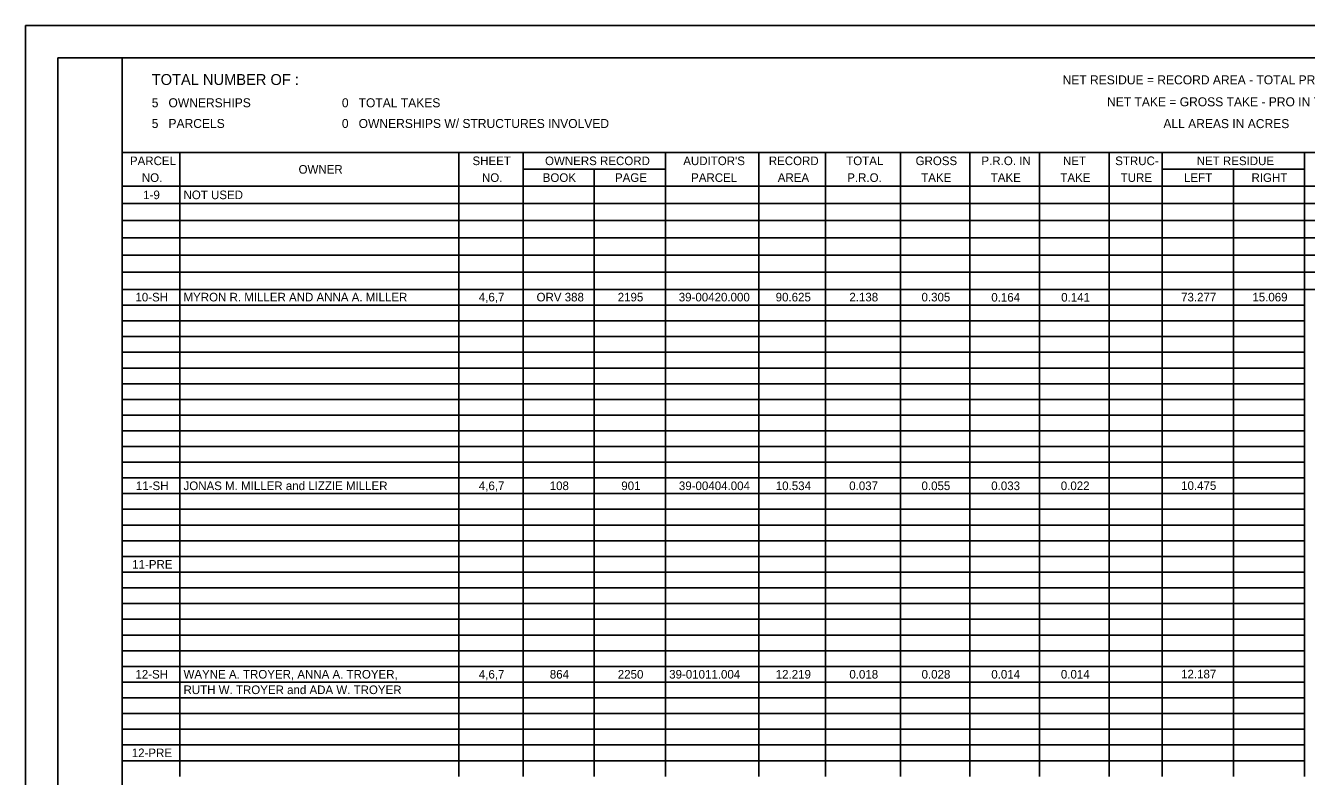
# Model space of a CAD drawing. Extents: x 0 to 34, y 0 to 22.
# Drawn here: x 0 to 19.9, y 10.33 to 22 of the extents above; entities that cross this region are included whole.
import ezdxf

# ---------------------------------------------------------------- set-up
doc = ezdxf.new("R2010")
doc.units = 0
for name, color, linetype in [('SH_Border', 7, 'Continuous'), ('SH_Cut_Line', 7, 'Continuous'), ('SH_Text', 7, 'Continuous')]:
    doc.layers.add(name, color=color, linetype=linetype)

msp = doc.modelspace()

# ---------------------------------------------------------------- linework, layer by layer
at = {"layer": 'SH_Border'}
for points in [[(0.5, 21.5), (1.5, 21.5), (1.5, 0.5), (0.5, 0.5)], [(1.5, 21.5), (33.5, 21.5), (33.5, 0.5), (1.5, 0.5)]]:
    msp.add_lwpolyline(points, close=True, dxfattribs=at)
at = {"layer": 'SH_Cut_Line'}
msp.add_lwpolyline([(0, 0), (34, 0), (34, 22), (0, 22)], close=True, dxfattribs=at)
at = {"layer": 'SH_Text'}
for p, q in [((1.5, 20.027), (7.73, 20.027)), ((1.5, 20.027), (1.5, 18.702)), ((2.395, 20.027), (2.395, 18.434)), ((6.731, 20.027), (6.731, 18.434)), ((7.73, 20.027), (14.669, 20.027)), ((7.73, 20.027), (7.73, 18.434)), ((9.939, 20.027), (9.939, 18.434)), ((11.392, 20.027), (11.392, 18.434)), ((12.426, 20.027), (12.426, 18.434)), ((13.588, 20.027), (13.588, 18.434)), ((14.669, 20.027), (32, 20.027)), ((14.669, 20.027), (14.669, 18.434)), ((15.75, 20.027), (15.75, 18.434)), ((16.831, 20.027), (16.831, 18.434)), ((17.657, 20.027), (17.657, 18.434)), ((19.865, 20.027), (19.865, 18.434)), ((7.73, 19.771), (9.939, 19.771)), ((8.834, 19.771), (8.834, 18.434)), ((17.657, 19.771), (19.865, 19.771)), ((18.761, 19.771), (18.761, 18.434)), ((1.5, 19.504), (7.73, 19.504)), ((7.73, 19.504), (14.669, 19.504)), ((14.669, 19.504), (32, 19.504)), ((1.5, 19.237), (7.73, 19.237)), ((7.73, 19.237), (14.669, 19.237)), ((14.669, 19.237), (32, 19.237)), ((1.5, 18.969), (7.73, 18.969)), ((7.73, 18.969), (14.669, 18.969)), ((14.669, 18.969), (32, 18.969)), ((1.5, 18.702), (7.73, 18.702)), ((7.73, 18.702), (14.669, 18.702)), ((14.669, 18.702), (32, 18.702)), ((1.5, 18.434), (7.73, 18.434)), ((2.395, 18.434), (2.395, 18.167)), ((6.731, 18.434), (6.731, 18.167)), ((7.73, 18.434), (14.669, 18.434)), ((7.73, 18.434), (7.73, 18.167)), ((8.834, 18.434), (8.834, 18.167)), ((9.939, 18.434), (9.939, 18.167)), ((11.392, 18.434), (11.392, 18.167)), ((12.426, 18.434), (12.426, 18.167)), ((13.588, 18.434), (13.588, 18.167)), ((14.669, 18.434), (32, 18.434)), ((14.669, 18.434), (14.669, 18.167)), ((15.75, 18.434), (15.75, 18.167)), ((16.831, 18.434), (16.831, 18.167)), ((17.657, 18.434), (17.657, 18.167)), ((18.761, 18.434), (18.761, 18.167)), ((19.865, 18.434), (19.865, 18.167)), ((1.5, 18.167), (7.73, 18.167)), ((2.395, 18.167), (2.395, 17.9)), ((6.731, 18.167), (6.731, 17.9)), ((7.73, 18.167), (14.669, 18.167)), ((7.73, 18.167), (7.73, 17.9)), ((8.834, 18.167), (8.834, 17.9)), ((9.939, 18.167), (9.939, 17.9)), ((11.392, 18.167), (11.392, 17.9)), ((12.426, 18.167), (12.426, 17.9)), ((13.588, 18.167), (13.588, 17.9)), ((14.669, 18.167), (32, 18.167)), ((14.669, 18.167), (14.669, 17.9)), ((15.75, 18.167), (15.75, 17.9)), ((16.831, 18.167), (16.831, 17.9)), ((17.657, 18.167), (17.657, 17.9)), ((18.761, 18.167), (18.761, 17.9)), ((19.865, 18.167), (19.865, 17.9)), ((1.5, 17.9), (7.73, 17.9)), ((2.395, 17.9), (2.395, 15.947)), ((6.731, 17.9), (6.731, 15.947)), ((7.73, 17.9), (14.669, 17.9)), ((7.73, 17.9), (7.73, 15.947)), ((8.834, 17.9), (8.834, 15.947)), ((9.939, 17.9), (9.939, 15.947)), ((11.392, 17.9), (11.392, 15.947)), ((12.426, 17.9), (12.426, 15.947)), ((13.588, 17.9), (13.588, 15.947)), ((14.669, 17.9), (32, 17.9)), ((14.669, 17.9), (14.669, 15.947)), ((15.75, 17.9), (15.75, 15.947)), ((16.831, 17.9), (16.831, 15.947)), ((17.657, 17.9), (17.657, 15.947)), ((18.761, 17.9), (18.761, 15.947)), ((19.865, 17.9), (19.865, 15.947)), ((1.5, 17.656), (7.73, 17.656)), ((7.73, 17.656), (14.669, 17.656)), ((14.669, 17.656), (19.865, 17.656)), ((1.5, 17.412), (7.73, 17.412)), ((7.73, 17.412), (14.669, 17.412)), ((14.669, 17.412), (19.865, 17.412)), ((1.5, 17.168), (7.73, 17.168)), ((7.73, 17.168), (14.669, 17.168)), ((14.669, 17.168), (19.865, 17.168)), ((1.5, 16.923), (7.73, 16.923)), ((7.73, 16.923), (14.669, 16.923)), ((14.669, 16.923), (19.865, 16.923)), ((1.5, 16.679), (7.73, 16.679)), ((7.73, 16.679), (14.669, 16.679)), ((14.669, 16.679), (19.865, 16.679)), ((1.5, 16.435), (7.73, 16.435)), ((7.73, 16.435), (14.669, 16.435)), ((14.669, 16.435), (19.865, 16.435)), ((1.5, 16.191), (7.73, 16.191)), ((7.73, 16.191), (14.669, 16.191)), ((14.669, 16.191), (19.865, 16.191)), ((1.5, 15.947), (7.73, 15.947)), ((2.395, 15.947), (2.395, 15.703)), ((6.731, 15.947), (6.731, 15.703)), ((7.73, 15.947), (14.669, 15.947)), ((7.73, 15.947), (7.73, 15.703)), ((8.834, 15.947), (8.834, 15.703)), ((9.939, 15.947), (9.939, 15.703)), ((11.392, 15.947), (11.392, 15.703)), ((12.426, 15.947), (12.426, 15.703)), ((13.588, 15.947), (13.588, 15.703)), ((14.669, 15.947), (19.865, 15.947)), ((14.669, 15.947), (14.669, 15.703)), ((15.75, 15.947), (15.75, 15.703)), ((16.831, 15.947), (16.831, 15.703)), ((17.657, 15.947), (17.657, 15.703)), ((18.761, 15.947), (18.761, 15.703)), ((19.865, 15.947), (19.865, 15.703)), ((1.5, 15.703), (7.73, 15.703)), ((2.395, 15.703), (2.395, 15.215)), ((6.731, 15.703), (6.731, 15.215)), ((7.73, 15.703), (14.669, 15.703)), ((7.73, 15.703), (7.73, 15.215)), ((8.834, 15.703), (8.834, 15.215)), ((9.939, 15.703), (9.939, 15.215)), ((11.392, 15.703), (11.392, 15.215)), ((12.426, 15.703), (12.426, 15.215)), ((13.588, 15.703), (13.588, 15.215)), ((14.669, 15.703), (19.865, 15.703)), ((14.669, 15.703), (14.669, 15.215)), ((15.75, 15.703), (15.75, 15.215)), ((16.831, 15.703), (16.831, 15.215)), ((17.657, 15.703), (17.657, 15.215)), ((18.761, 15.703), (18.761, 15.215)), ((19.865, 15.703), (19.865, 15.215)), ((1.5, 15.459), (7.73, 15.459)), ((7.73, 15.459), (14.669, 15.459)), ((14.669, 15.459), (19.865, 15.459)), ((1.5, 15.215), (7.73, 15.215)), ((2.395, 15.215), (2.395, 14.971)), ((6.731, 15.215), (6.731, 14.971)), ((7.73, 15.215), (14.669, 15.215)), ((7.73, 15.215), (7.73, 14.971)), ((8.834, 15.215), (8.834, 14.971)), ((9.939, 15.215), (9.939, 14.971)), ((11.392, 15.215), (11.392, 14.971)), ((12.426, 15.215), (12.426, 14.971)), ((13.588, 15.215), (13.588, 14.971)), ((14.669, 15.215), (19.865, 15.215)), ((14.669, 15.215), (14.669, 14.971)), ((15.75, 15.215), (15.75, 14.971)), ((16.831, 15.215), (16.831, 14.971)), ((17.657, 15.215), (17.657, 14.971)), ((18.761, 15.215), (18.761, 14.971)), ((19.865, 15.215), (19.865, 14.971)), ((1.5, 14.971), (7.73, 14.971)), ((1.5, 14.971), (1.5, 14.727)), ((2.395, 14.971), (2.395, 14.727)), ((6.731, 14.971), (6.731, 14.727)), ((7.73, 14.971), (14.669, 14.971)), ((7.73, 14.971), (7.73, 14.727)), ((8.834, 14.971), (8.834, 14.727)), ((9.939, 14.971), (9.939, 14.727)), ((11.392, 14.971), (11.392, 14.727)), ((12.426, 14.971), (12.426, 14.727)), ((13.588, 14.971), (13.588, 14.727)), ((14.669, 14.971), (19.865, 14.971)), ((14.669, 14.971), (14.669, 14.727)), ((15.75, 14.971), (15.75, 14.727)), ((16.831, 14.971), (16.831, 14.727)), ((17.657, 14.971), (17.657, 14.727)), ((18.761, 14.971), (18.761, 14.727)), ((19.865, 14.971), (19.865, 14.727)), ((1.5, 14.727), (7.73, 14.727)), ((1.5, 14.727), (1.5, 14.483)), ((2.395, 14.727), (2.395, 14.483)), ((6.731, 14.727), (6.731, 14.483)), ((7.73, 14.727), (14.669, 14.727)), ((7.73, 14.727), (7.73, 14.483)), ((8.834, 14.727), (8.834, 14.483)), ((9.939, 14.727), (9.939, 14.483)), ((11.392, 14.727), (11.392, 14.483)), ((12.426, 14.727), (12.426, 14.483)), ((13.588, 14.727), (13.588, 14.483)), ((14.669, 14.727), (19.865, 14.727)), ((14.669, 14.727), (14.669, 14.483)), ((15.75, 14.727), (15.75, 14.483)), ((16.831, 14.727), (16.831, 14.483)), ((17.657, 14.727), (17.657, 14.483)), ((18.761, 14.727), (18.761, 14.483)), ((19.865, 14.727), (19.865, 14.483)), ((1.5, 14.483), (7.73, 14.483)), ((1.5, 14.483), (1.5, 10.821)), ((2.395, 14.483), (2.395, 10.821)), ((6.731, 14.483), (6.731, 10.821)), ((7.73, 14.483), (14.669, 14.483)), ((7.73, 14.483), (7.73, 10.821)), ((8.834, 14.483), (8.834, 10.821)), ((9.939, 14.483), (9.939, 10.821)), ((11.392, 14.483), (11.392, 10.821)), ((12.426, 14.483), (12.426, 10.821)), ((13.588, 14.483), (13.588, 10.821)), ((14.669, 14.483), (19.865, 14.483)), ((14.669, 14.483), (14.669, 10.821)), ((15.75, 14.483), (15.75, 10.821)), ((16.831, 14.483), (16.831, 10.821)), ((17.657, 14.483), (17.657, 10.821)), ((18.761, 14.483), (18.761, 10.821)), ((19.865, 14.483), (19.865, 10.821)), ((1.5, 14.238), (7.73, 14.238)), ((7.73, 14.238), (14.669, 14.238)), ((14.669, 14.238), (19.865, 14.238)), ((1.5, 13.994), (7.73, 13.994)), ((7.73, 13.994), (14.669, 13.994)), ((14.669, 13.994), (19.865, 13.994)), ((1.5, 13.75), (7.73, 13.75)), ((7.73, 13.75), (14.669, 13.75)), ((14.669, 13.75), (19.865, 13.75)), ((1.5, 13.506), (7.73, 13.506)), ((7.73, 13.506), (14.669, 13.506)), ((14.669, 13.506), (19.865, 13.506)), ((1.5, 13.262), (7.73, 13.262)), ((7.73, 13.262), (14.669, 13.262)), ((14.669, 13.262), (19.865, 13.262)), ((1.5, 13.018), (7.73, 13.018)), ((7.73, 13.018), (14.669, 13.018)), ((14.669, 13.018), (19.865, 13.018)), ((1.5, 12.774), (7.73, 12.774)), ((7.73, 12.774), (14.669, 12.774)), ((14.669, 12.774), (19.865, 12.774)), ((1.5, 12.53), (7.73, 12.53)), ((7.73, 12.53), (14.669, 12.53)), ((14.669, 12.53), (19.865, 12.53)), ((1.5, 12.286), (7.73, 12.286)), ((7.73, 12.286), (14.669, 12.286)), ((14.669, 12.286), (19.865, 12.286)), ((1.5, 12.042), (7.73, 12.042)), ((7.73, 12.042), (14.669, 12.042)), ((14.669, 12.042), (19.865, 12.042)), ((1.5, 11.797), (7.73, 11.797)), ((7.73, 11.797), (14.669, 11.797)), ((14.669, 11.797), (19.865, 11.797)), ((1.5, 11.553), (7.73, 11.553)), ((7.73, 11.553), (14.669, 11.553)), ((14.669, 11.553), (19.865, 11.553)), ((1.5, 11.309), (7.73, 11.309)), ((7.73, 11.309), (14.669, 11.309)), ((14.669, 11.309), (19.865, 11.309)), ((1.5, 11.065), (7.73, 11.065)), ((7.73, 11.065), (14.669, 11.065)), ((14.669, 11.065), (19.865, 11.065)), ((1.5, 10.821), (7.73, 10.821)), ((1.5, 10.821), (1.5, 10.577)), ((2.395, 10.821), (2.395, 10.577)), ((6.731, 10.821), (6.731, 10.577)), ((7.73, 10.821), (14.669, 10.821)), ((7.73, 10.821), (7.73, 10.577)), ((8.834, 10.821), (8.834, 10.577)), ((9.939, 10.821), (9.939, 10.577)), ((11.392, 10.821), (11.392, 10.577)), ((12.426, 10.821), (12.426, 10.577)), ((13.588, 10.821), (13.588, 10.577)), ((14.669, 10.821), (19.865, 10.821)), ((14.669, 10.821), (14.669, 10.577)), ((15.75, 10.821), (15.75, 10.577)), ((16.831, 10.821), (16.831, 10.577)), ((17.657, 10.821), (17.657, 10.577)), ((18.761, 10.821), (18.761, 10.577)), ((19.865, 10.821), (19.865, 10.577)), ((1.5, 10.577), (7.73, 10.577)), ((1.5, 10.577), (1.5, 10.333)), ((2.395, 10.577), (2.395, 10.333)), ((6.731, 10.577), (6.731, 10.333)), ((7.73, 10.577), (14.669, 10.577)), ((7.73, 10.577), (7.73, 10.333)), ((8.834, 10.577), (8.834, 10.333)), ((9.939, 10.577), (9.939, 10.333)), ((11.392, 10.577), (11.392, 10.333)), ((12.426, 10.577), (12.426, 10.333)), ((13.588, 10.577), (13.588, 10.333)), ((14.669, 10.577), (19.865, 10.577)), ((14.669, 10.577), (14.669, 10.333)), ((15.75, 10.577), (15.75, 10.333)), ((16.831, 10.577), (16.831, 10.333)), ((17.657, 10.577), (17.657, 10.333)), ((18.761, 10.577), (18.761, 10.333)), ((19.865, 10.577), (19.865, 10.333))]:
    msp.add_line(p, q, dxfattribs=at)

# ---------------------------------------------------------------- texts
for s, height, p in [('TOTAL NUMBER OF :', 0.17, (1.959, 21.077)), ('NET RESIDUE = RECORD AREA - TOTAL PRO - NET TAKE', 0.14, (16.108, 21.087)), ('5   OWNERSHIPS', 0.14, (1.959, 20.731)), ('0   TOTAL TAKES', 0.14, (4.913, 20.731)), ('NET TAKE = GROSS TAKE - PRO IN TAKE', 0.14, (16.799, 20.746)), ('5   PARCELS', 0.14, (1.959, 20.409)), ('0   OWNERSHIPS W/ STRUCTURES INVOLVED', 0.14, (4.913, 20.409)), ('ALL AREAS IN ACRES', 0.14, (17.674, 20.407)), ('PARCEL', 0.1337, (1.62, 19.832)), ('SHEET', 0.1337, (6.942, 19.832)), ('OWNERS RECORD', 0.13367, (8.069, 19.832)), ("AUDITOR'S", 0.1337, (10.216, 19.832)), ('RECORD', 0.1337, (11.545, 19.832)), ('TOTAL', 0.1337, (12.747, 19.832)), ('GROSS', 0.1337, (13.825, 19.832)), ('P.R.O. IN', 0.1337, (14.848, 19.832)), ('NET', 0.1337, (16.114, 19.832)), ('STRUC-', 0.1337, (16.926, 19.832)), ('NET RESIDUE', 0.13367, (18.192, 19.832)), ('NO.', 0.1337, (1.806, 19.571)), ('OWNER', 0.1337, (4.24, 19.699)), ('NO.', 0.1337, (7.089, 19.571)), ('BOOK', 0.1337, (8.033, 19.571)), ('PAGE', 0.1337, (9.155, 19.571)), ('PARCEL', 0.1337, (10.338, 19.571)), ('AREA', 0.1337, (11.684, 19.571)), ('P.R.O.', 0.1337, (12.763, 19.571)), ('TAKE', 0.1337, (13.912, 19.571)), ('TAKE', 0.1337, (14.993, 19.571)), ('TAKE', 0.1337, (16.074, 19.571)), ('TURE', 0.1337, (17.011, 19.571)), ('LEFT', 0.1337, (17.995, 19.571)), ('RIGHT', 0.1337, (19.043, 19.571)), ('1-9', 0.1337, (1.827, 19.303)), ('NOT USED', 0.1337, (2.453, 19.303)), ('10-SH', 0.1337, (1.706, 17.714)), ('MYRON R. MILLER AND ANNA A. MILLER', 0.13367, (2.453, 17.714)), ('4,6,7', 0.1337, (7.04, 17.714)), ('ORV 388', 0.1337, (7.937, 17.714)), ('2195', 0.1337, (9.198, 17.714)), ('39-00420.000', 0.13367, (10.146, 17.714)), ('90.625', 0.1337, (11.651, 17.714)), ('2.138', 0.1337, (12.796, 17.714)), ('0.305', 0.1337, (13.917, 17.714)), ('0.164', 0.1337, (15.001, 17.711)), ('0.141', 0.1337, (16.087, 17.711)), ('73.277', 0.1337, (17.949, 17.714)), ('15.069', 0.1337, (19.056, 17.714)), ('JONAS M. MILLER and LIZZIE MILLER', 0.13367, (2.453, 14.782)), ('11-SH', 0.1337, (1.713, 14.782)), ('4,6,7', 0.1337, (7.04, 14.782)), ('108', 0.1337, (8.141, 14.782)), ('901', 0.1337, (9.253, 14.782)), ('39-00404.004', 0.13367, (10.148, 14.782)), ('10.534', 0.1337, (11.653, 14.782)), ('0.037', 0.1337, (12.794, 14.782)), ('0.055', 0.1337, (13.917, 14.782)), ('0.033', 0.1337, (15, 14.782)), ('0.022', 0.1337, (16.08, 14.782)), ('10.475', 0.1337, (17.95, 14.785)), ('11-PRE', 0.1337, (1.656, 13.561)), ('12-SH', 0.1337, (1.706, 11.853)), ('WAYNE A. TROYER, ANNA A. TROYER,', 0.13367, (2.453, 11.853)), ('4,6,7', 0.1337, (7.04, 11.853)), ('864', 0.1337, (8.143, 11.853)), ('2250', 0.1337, (9.199, 11.853)), ('39-01011.004', 0.13367, (9.997, 11.853)), ('12.219', 0.1337, (11.652, 11.853)), ('0.018', 0.1337, (12.796, 11.853)), ('0.028', 0.1337, (13.918, 11.853)), ('0.014', 0.1337, (15.001, 11.853)), ('0.014', 0.1337, (16.082, 11.853)), ('12.187', 0.1337, (17.949, 11.856)), ('RUTH W. TROYER and ADA W. TROYER', 0.13367, (2.453, 11.612)), ('12-PRE', 0.1337, (1.649, 10.632))]:
    msp.add_text(s, height=height, dxfattribs=at).set_placement(p)

doc.saveas('drawing.dxf')
